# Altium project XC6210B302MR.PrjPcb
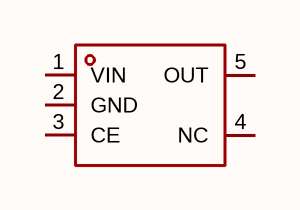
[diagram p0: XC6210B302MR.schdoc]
1 sheet, 1 parts. Net scope: global (net labels, ports and power ports of the same name join across sheets).

## Sheet XC6210B302MR.schdoc
size 127 x 101 mm

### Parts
U?  xc6210b302mr  [SOT-23-5_L2.9-W1.6-P0.95-LS2.8-BR]  (value not drawn)

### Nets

Not connected (* = marked no-connect by the designer): U? 1(VIN) 2(GND) 3(CE) 4(NC) 5(OUT)

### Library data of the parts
U? = xc6210b302mr: 输出极性:正极;工作电压:6V;输出电压:3V;输出电流:800mA;电源纹波抑制比(PSRR):50dB@(10kHz);输出类型:固定;; Manufacturer: TECH PUBLIC(台舟); AddInBom: yes; ModelId: 7ba65df16e7b4570af156e925f9c37fe; ModelTransform: 114.173,114.173,0,90,0,0,0,0,0; Output Configuration: 正极; Voltage - Supply: 6V; Output Voltage: 3V; Output Current: 800mA; Voltage Dropout: 400mV@(800mA); standby current: 25uA; Output Type: 固定; Number of Outputs: 1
